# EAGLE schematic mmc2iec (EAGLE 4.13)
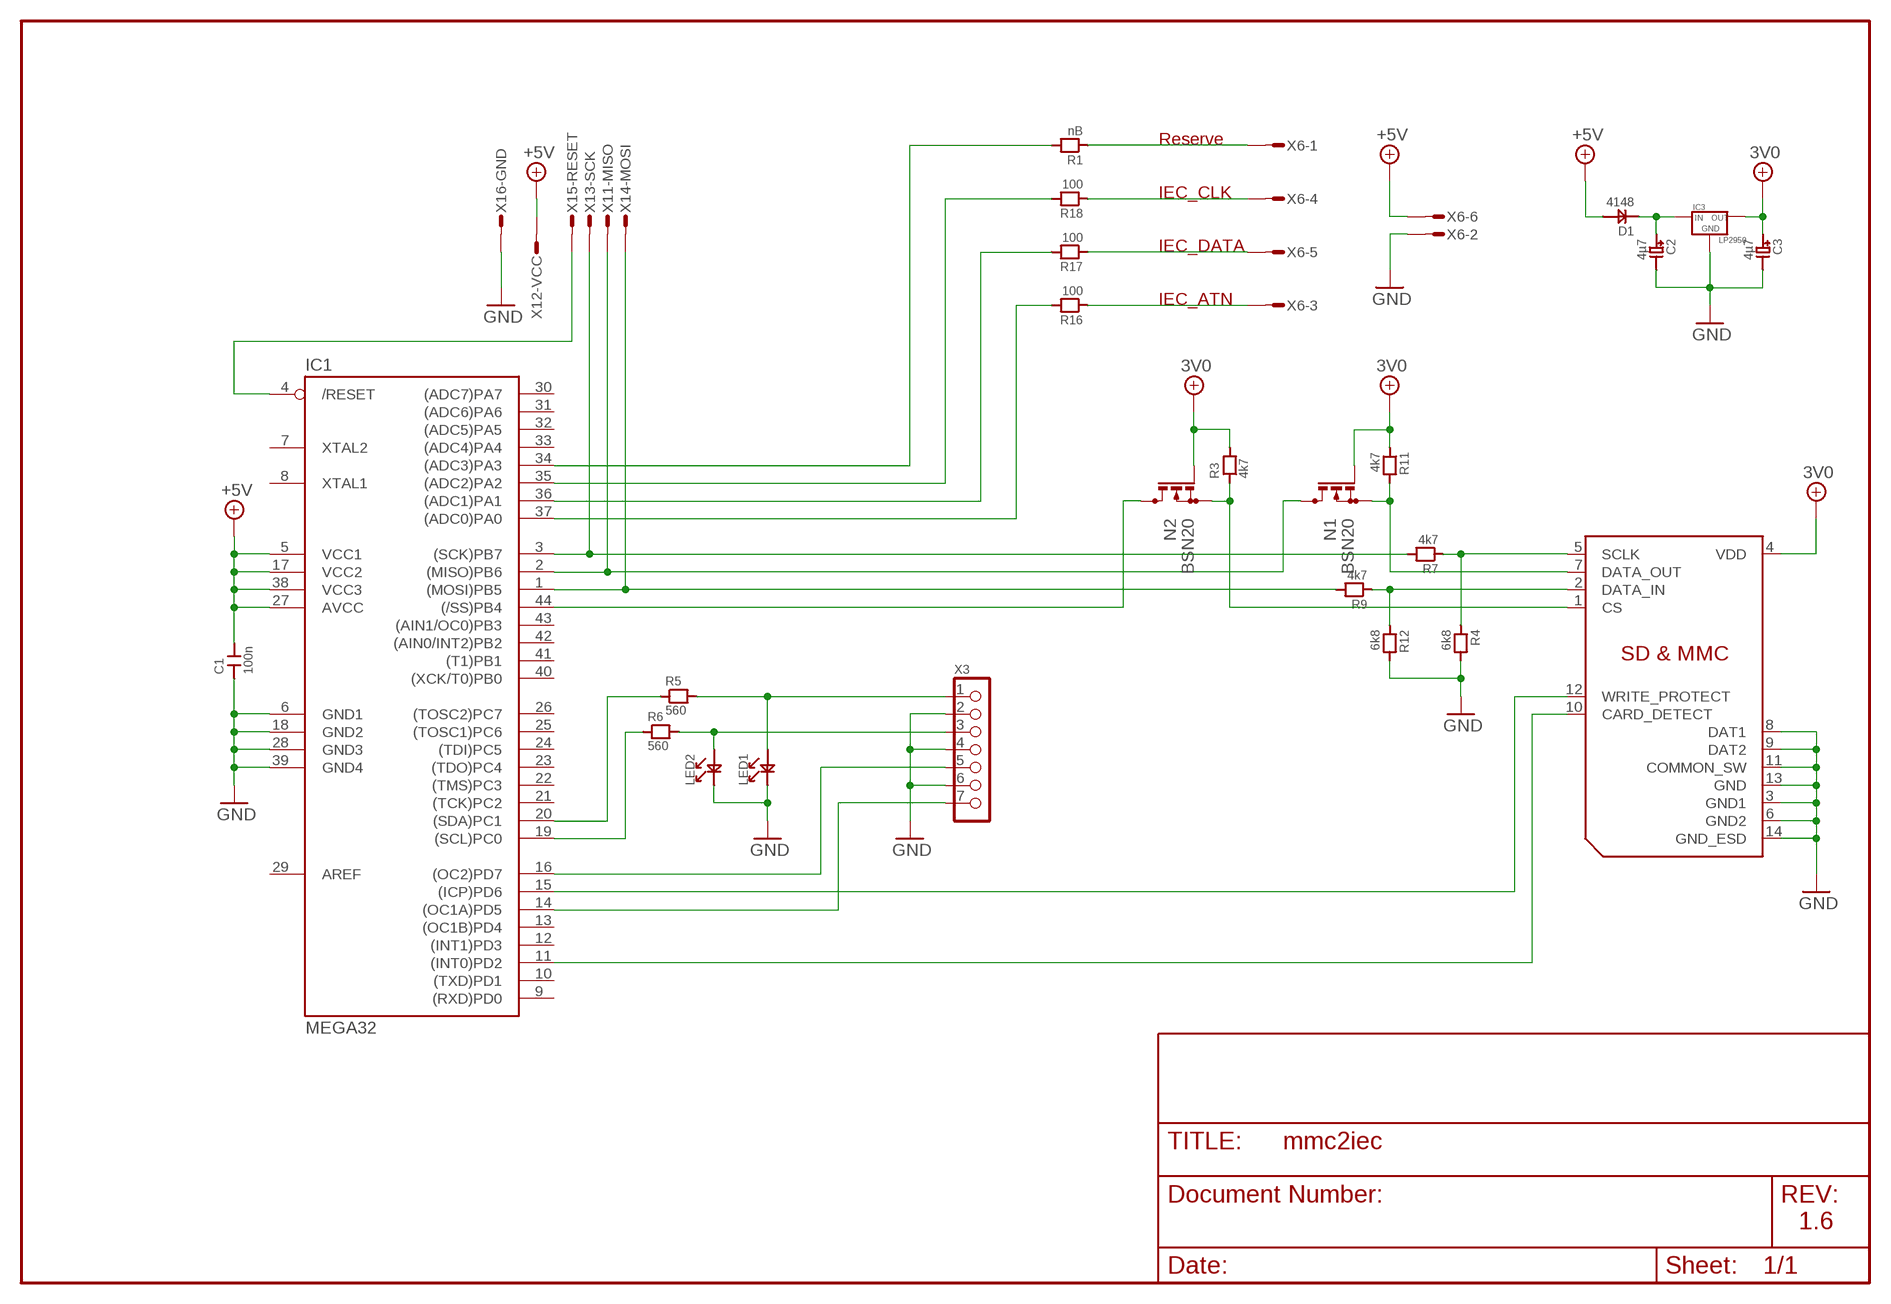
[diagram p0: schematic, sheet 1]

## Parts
C1  100n  C0805  [C0805]
C2  4µ7  C_POLTA_A  [C_TANTAL_A]
C3  4µ7  C_POLTA_A  [C_TANTAL_A]
D1  4148  DSOD-123  [SOD-123]
IC1  MEGA32  MEGA16/32TQFP  [TQFP44]
IC3  LP2950  [TO92]
LED1  LED0805  [LED0805]
LED2  LED0805  [LED0805]
N1  BSN20  [SOT23]
N2  BSN20  [SOT23]
R1  nB  R0805  [R0805]
R3  4k7  R0805  [R0805]
R4  6k8  R0805  [R0805]
R5  560  R0805  [R0805]
R6  560  R0805  [R0805]
R7  4k7  R0805  [R0805]
R9  4k7  R0805  [R0805]
R11  4k7  R0805  [R0805]
R12  6k8  R0805  [R0805]
R16  100  R0805  [R0805]
R17  100  R0805  [R0805]
R18  100  R0805  [R0805]
X1  AVR-ISP_1X6  [1X6_ISP]
X2  SD_SCDA1A1401  [ALPS_SCDA1A1401]
X3  PINH1X7_2,54  [1X7]
X6  MICROMATCH-6_PIN  [MICROMATCH-6]

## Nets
3V0: C3.1 IC3.3(OUT) N1.1(G) N2.1(G) R3.2 R11.1 X2.4(VDD)
+5V: C1.2 D1.2 IC1.5(VCC1) IC1.17(VCC2) IC1.27(AVCC) IC1.38(VCC3) X1.2 X6.6
/RESET: IC1.4(/RESET) X1.5
ATN: IC1.37((ADC0)PA0) R16.2
CD: IC1.11((INT0)PD2) X2.10(CARD_DETECT)
CLK: IC1.35((ADC2)PA2) R18.2
DATA: IC1.36((ADC1)PA1) R17.2
GND: C1.1 C2.2 C3.2 IC1.6(GND1) IC1.18(GND2) IC1.28(GND3) IC1.39(GND4) IC3.2(GND) LED1.1 LED2.1 R4.2 R12.2 X1.6 X2.3(GND1) X2.6(GND2) X2.8(DAT1) X2.9(DAT2) X2.11(COMMON_SW) X2.13(GND) X2.14(GND_ESD) X3.2 X3.4 X3.6 X6.2
MISO: IC1.2((MISO)PB6) N1.3(D) X1.1
MOSI: IC1.1((MOSI)PB5) R9.2 X1.4
N$1: IC1.14((OC1A)PD5) X3.7
N$2: C2.1 D1.1 IC3.1(IN)
N$3: R4.1 R7.1 X2.5(SCLK)
N$4: N1.2(S) R11.2 X2.7(DATA_OUT)
N$5: R9.1 R12.1 X2.2(DATA_IN)
N$6: IC1.44((/SS)PB4) N2.3(D)
N$7: R18.1 X6.4
N$8: LED1.2 R5.2 X3.1
N$9: LED2.2 R6.2 X3.3
N$10: IC1.16((OC2)PD7) X3.5
N$11: R17.1 X6.5
N$12: R16.1 X6.3
N$13: R1.1 X6.1
N$14: IC1.34((ADC3)PA3) R1.2
PC0: IC1.19((SCL)PC0) R6.1
PC1: IC1.20((SDA)PC1) R5.1
SCK: IC1.3((SCK)PB7) R7.2 X1.3
SS: N2.2(S) R3.1 X2.1(CS)
WP: IC1.15((ICP)PD6) X2.12(WRITE_PROTECT)
Unconnected: IC1.7(XTAL2) IC1.8(XTAL1) IC1.9((RXD)PD0) IC1.10((TXD)PD1) IC1.12((INT1)PD3) IC1.13((OC1B)PD4) IC1.21((TCK)PC2) IC1.22((TMS)PC3) IC1.23((TDO)PC4) IC1.24((TDI)PC5) IC1.25((TOSC1)PC6) IC1.26((TOSC2)PC7) IC1.29(AREF) IC1.30((ADC7)PA7) IC1.31((ADC6)PA6) IC1.32((ADC5)PA5) IC1.33((ADC4)PA4) IC1.40((XCK/T0)PB0) IC1.41((T1)PB1) IC1.42((AIN0/INT2)PB2) IC1.43((AIN1/OC0)PB3)

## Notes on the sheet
- Reserve
- IEC_CLK
- IEC_DATA
- IEC_ATN
- 1.6

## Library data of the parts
C1 = 0_rr:C
C2 C3 = 0_rr:C_POL
D1 = 0_rr:D
IC1 = 0_rr:MEGA16/32: MICROCONTROLLER 16 Kbytes FLASH, 512 bytes EEPROM 1 Kbytes SRAM dual UART hardware multiplier
IC3 = 0_rr:LP2950
LED1 LED2 = 0_rr:LED
N1 N2 = 0_rr:BSN20: N-CHANNEL MOS FET
R1 R3-R7 R9 R11 R12 R16-R18 = 0_rr:R
X1 = 0_rr:AVR-ISP: MicroMaTch 6 7-215464-6 / 0-215464-6 Drawing Number C-215464 DDEController.pdf
X2 = 0_rr:SD
X3 = 0_rr:PINH1X7
X6 = 0_rr:MICROMATCH-6: MicroMaTch 6 7-215464-6 / 0-215464-6 Drawing Number C-215464 DDEController.pdf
